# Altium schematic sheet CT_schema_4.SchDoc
size 422 x 246 mm
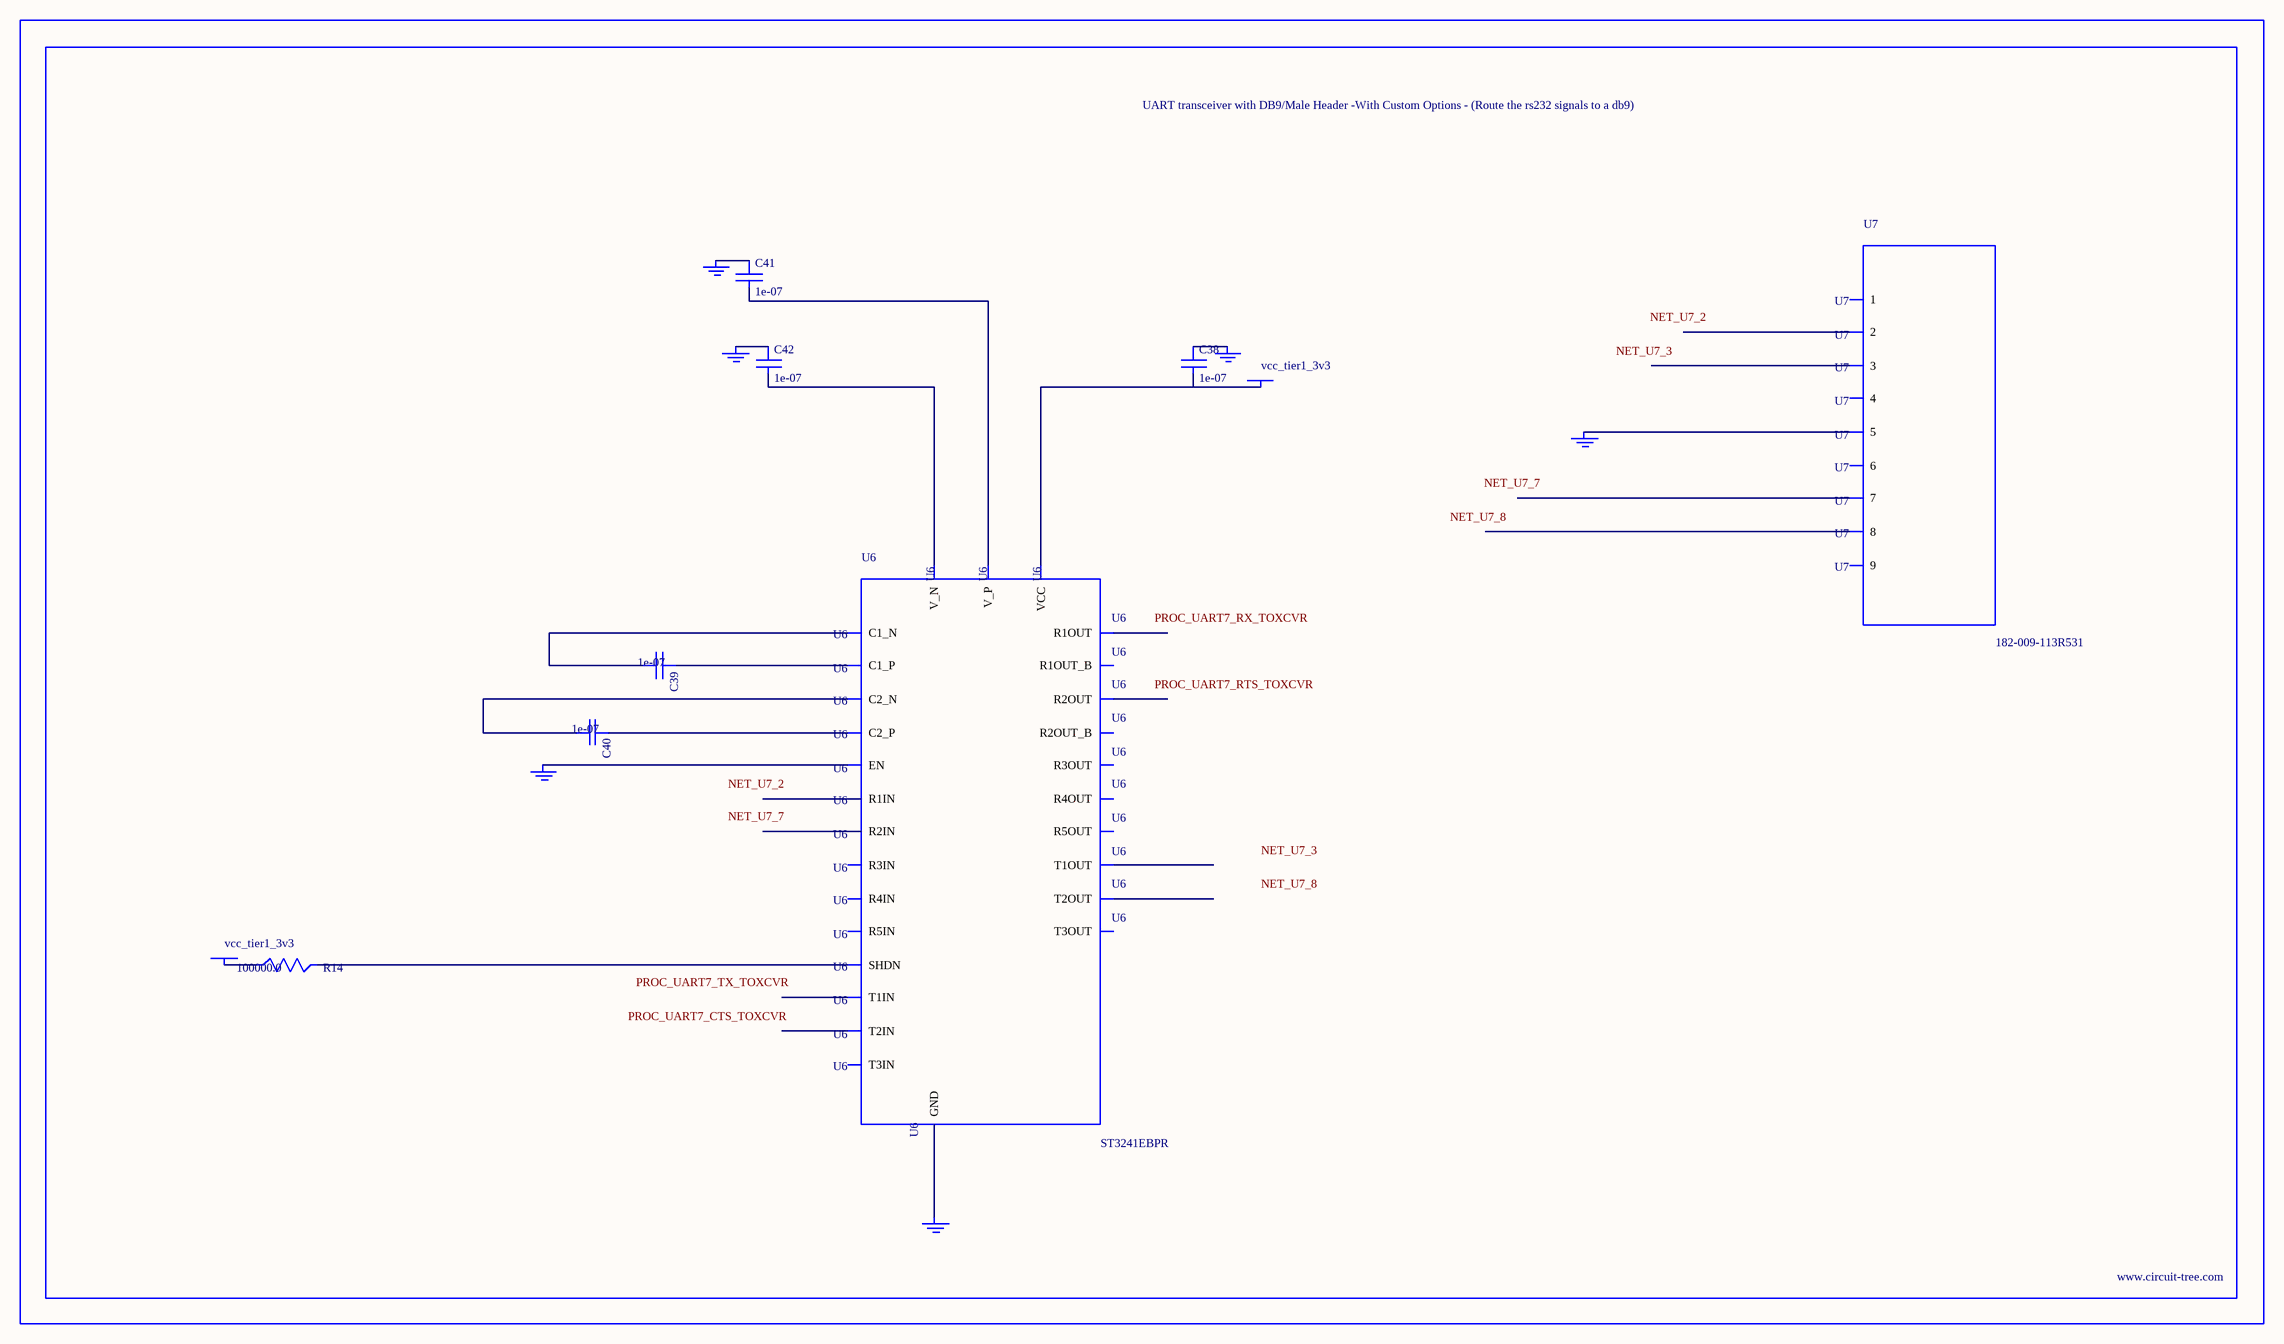
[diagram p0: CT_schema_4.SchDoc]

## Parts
BORDER3  (no value)
C38  1e-07  [C0402]
C39  1e-07  [C0402]
C40  1e-07  [C0402]
C41  1e-07  [C0402]
C42  1e-07  [C0402]
GND_INSTANCE_3_0  (no value)
GND_INSTANCE_3_1  (no value)
GND_INSTANCE_3_2  (no value)
GND_INSTANCE_3_3  (no value)
GND_INSTANCE_3_4  (no value)
GND_INSTANCE_3_5  (no value)
POWER_INSTANCE_3_0  vcc_tier1_3v3
POWER_INSTANCE_3_1  vcc_tier1_3v3
R14  100000.0  [R0603]
U6  ST3241EBPR  [SSOP-28]
U7  182-009-113R531  [182-009-MALE]

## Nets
NetC38_1: C38.1 GND_INSTANCE_3_2.0(GND)
NetC38_2: C38.2 POWER_INSTANCE_3_1.0(PWR) U6.26(VCC)
NetC39_1: C39.1 U6.28(C1_P)
NetC39_2: C39.2 U6.24(C1_N)
NetC40_1: C40.1 U6.1(C2_P)
NetC40_2: C40.2 U6.2(C2_N)
NetC41_1: C41.1 GND_INSTANCE_3_3.0(GND)
NetC41_2: C41.2 U6.27(V_P)
NetC42_1: C42.1 GND_INSTANCE_3_0.0(GND)
NetC42_2: C42.2 U6.3(V_N)
NetGND_INSTANCE_3_1_0: GND_INSTANCE_3_1.0(GND) U6.23(EN)
NetGND_INSTANCE_3_4_0: GND_INSTANCE_3_4.0(GND) U6.25(GND)
NetGND_INSTANCE_3_5_0: GND_INSTANCE_3_5.0(GND) U7.5
NetPOWER_INSTANCE_3_0_0: POWER_INSTANCE_3_0.0(PWR) R14.1
NetR14_2: R14.2 U6.22(SHDN)

Not connected (* = marked no-connect by the designer): U6 4(R1IN) 5(R2IN) 6(R3IN) 7(R4IN) 8(R5IN) 9(T1OUT) 10(T2OUT) 11(T3OUT) 12(T3IN) 13(T2IN) 14(T1IN) 15(R5OUT) 16(R4OUT) 17(R3OUT) 18(R2OUT) 19(R1OUT) 20(R2OUT_B) 21(R1OUT_B); U7 1 2 3 4 6 7 8 9

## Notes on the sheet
- Labels drawn without touching a wire or pin: NET_U7_2, NET_U7_3, NET_U7_7, NET_U7_8, PROC_UART7_CTS_TOXCVR, PROC_UART7_RTS_TOXCVR, PROC_UART7_RX_TOXCVR, PROC_UART7_TX_TOXCVR

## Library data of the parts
BORDER3 = BORDER_PAGE3
C38-C42 = C0402C104K3RACTU
GND_INSTANCE_3_0-GND_INSTANCE_3_5 = GND
POWER_INSTANCE_3_0 POWER_INSTANCE_3_1 = PWR
R14 = RC0603JR-07100KL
